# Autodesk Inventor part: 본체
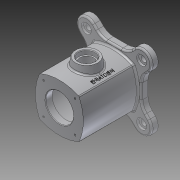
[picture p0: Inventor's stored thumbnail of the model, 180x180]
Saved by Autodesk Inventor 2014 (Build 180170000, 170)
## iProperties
Created: 2016-05
Part Number: 본체
Material: 알루미늄 6061
Document SubType Name: Modeling
Designer: J.H.Beak
Density: 2.71 g/cm^3
Appearance: 알루미늄 - 평지
Mass: 1114.45 g
Surface Area: 865.528 cm^2
Volume: 411.235 cm^3
Author: J.H.Beak
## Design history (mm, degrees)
sketch "스케치1"
  geometry: L1 (35.355, -35.355)-(-35.355, -35.355); L2 (-35.355, -35.355)-(-35.355, 35.355); L3 (-35.355, 35.355)-(35.355, 35.355); L4 (35.355, 35.355)-(35.355, -35.355); L5 (35.355, -35.355)-(-35.355, 35.355); L6 (-35.355, -35.355)-(35.355, 35.355); A1 r 85.579 centre (-42.579, 0) between (35.355, -35.355) and (35.355, 35.355); A2 r 85.579 centre (0, -42.579) between (35.355, 35.355) and (-35.355, 35.355); A3 r 85.579 centre (42.579, 0) between (-35.355, 35.355) and (-35.355, -35.355); A4 r 85.579 centre (0, 42.579) between (-35.355, -35.355) and (35.355, -35.355); 3 further points
  constraints: 12 end point, 8 point on circle, 4 centre point, 4 midpoint, 3 equal radius, 2 parallel, 2 perpendicular, 1 horizontal, 1 horizontal alignment
  dimensions: "d0" = 100 distance of L1.start L2.end; "d3" = 86 dimension on A3 A1
extrude "돌출1" new body sketch "스케치1" distance "d4" = 98; taper "d5" = 0 deg
fillet "모깎기1" dims "d6" = 3
sketch "스케치2"
  geometry: L1 (0, 0)-(-49.497, -49.497); L2 (-67.249, 0)-(61.375, 0) reference; L3 (49, -49)-(-49, -49); L4 (-49, -49)-(-49, 49); L5 (-49, 49)-(49, 49); L6 (49, 49)-(49, -49); L7 (49, -49)-(-49, 49); L8 (-49, -49)-(49, 49); L9 (-49.497, -49.497)-(0, 0); L10 (-62.225, -36.77)-(-12.728, 12.728); L11 (12.728, -12.728)-(-36.77, -62.225); A1 r 18 centre (-49.497, -49.497) between (-62.225, -36.77) and (-36.77, -62.225); A2 r 18 centre (0, 0) between (12.728, -12.728) and (-12.728, 12.728); 1 further point
  constraints: 22 end point, 4 equal length, 4 point on circle, 4 tangent, 3 midpoint, 2 centre point, 2 perpendicular, 1 horizontal
  dimensions: "d8" = 45 deg angle of L2 L1; "d9" = 70 distance of L1.start L1.end; "d10" = 98 distance of L4.end L5.end; "d11" = 36 distance between parallel lines of L10 L11
extrude "돌출2" join sketch "스케치2" distance "d12" = 12; taper "d13" = 0 deg
fillet "모깎기2" dims "d17" = 25
node "작업 평면1"
sketch "스케치3"
  geometry: L1 (-36.77, 12)-(-67.497, 12) reference; C1 r 20 at (0, -49); 2 further points
  constraints: 1 centre point, 1 vertical alignment
  dimensions: "d19" = 61 distance from line of L1 C1.centre; "d20" = 40 diameter of C1
extrude "돌출3" join sketch "스케치3" stored distance "d21" = 12; taper "d22" = 10 deg
sketch "스케치4"
  geometry: L1 (-98, 0)-(-86, 0); L2 (-86, 0)-(-86, 25); L3 (-86, 25)-(-98, 25); L4 (-98, 25)-(-98, 0); L5 (-86, 0)-(0, 0); L6 (0, 0)-(0, 35); L7 (0, 35)-(-86, 35); L8 (-86, 35)-(-86, 0); L9 (0, 0)-(12, 0); L10 (12, 0)-(12, 25); L11 (12, 25)-(0, 25); L12 (0, 25)-(0, 0); L13 (-98, 34.285)-(-98, -34.285) reference; L14 (12, -13.189)-(12, 13.189) reference; L15 (0, -34.285)-(0, 34.285) reference; 2 further points
  constraints: 24 end point, 6 parallel, 3 horizontal, 3 perpendicular, 2 collinear, 1 midpoint, 1 point on line
  dimensions: "d23" = 12 distance of L2.end L3.end; "d24" = 86 distance of L6.end L7.end; "d25" = 70 diameter of L7 L5; "d26" = 50 diameter of L11 L5; "d27" = 50 diameter of L3 L5
revolve "회전1" sketch "스케치4" stored, may be unused: angle "d28" = 90 deg
hole "구멍1" diameter "d31" = 25; stored, may be unused: countersink angle "d35" = 90 deg, drill point angle "d37" = 118 deg; dims "d29" = 10, "d30" = 10, "d32" = 6, "d33" = 30, "d34" = 8, "d36" = 8
chamfer "모따기1" distance "d38" = 1; stored, may be unused: second distance "d39" = 2, angle "d40" = 45 deg
fillet "모깎기3" dims "d41" = 3
fillet "모깎기4" dims "d42" = 3
fillet "모깎기5" dims "d43" = 3
fillet "모깎기6" dims "d44" = 3
hole "구멍2" diameter "d47" = 10; stored, may be unused: countersink angle "d51" = 90 deg, drill point angle "d53" = 118 deg; dims "d45" = 10, "d46" = 10, "d48" = 6, "d49" = 18, "d50" = 4, "d52" = 8
sketch "스케치5"
  geometry: L1 (0, 0)-(28.284, 28.284); L2 (-94.496, 0)-(94.496, 0) reference
  constraints: 2 end point
  dimensions: "d57" = 45 deg angle of L2 L1; "d58" = 40 distance of L1.start L1.end
hole "구멍3" sketch "스케치5" at (28.284, 28.284) diameter "d59" = 3.242; stored, may be unused: countersink angle "d63" = 90 deg, drill point angle "d65" = 118 deg; dims "d60" = 7, "d61" = 18, "d62" = 4, "d64" = 10
node "작업 평면3"
sketch "스케치6"
  geometry: L1 (0, -71)-(0, 83) reference; L2 (-34.285, -49)-(34.285, -49) reference; 2 further points
  constraints: 1 other
  dimensions: "d69" = 29 distance from line of L1 point (29, 0); "d70" = 49 distance from line of L2 point (29, 0)
feature "엠보싱1" sketch "스케치6" dims "d0" = 100, "d3" = 86, "d10" = 98, "d71" = 0.5, "d72" = 0
node "솔리드1"
pattern_circular "원형 패턴1" dims angle "d15" = 360 deg
pattern_circular "원형 패턴2" dims angle "d55" = 360 deg
pattern_circular "원형 패턴3" dims angle "d67" = 360 deg
mirror "대칭2"
other parameters: "d18" = 55
